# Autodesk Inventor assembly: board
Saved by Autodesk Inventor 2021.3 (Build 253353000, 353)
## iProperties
Created: 2021-12
Part Number: board
Document SubType Name: Assembly
Designer: Administrator
Title: board v1
Author: Administrator
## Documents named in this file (3)
- c:\worker\convert-fusion-r08\tmp\job-1\42\output\files\5687be83-607c-4978-9340-54991ac6dc59\board v1.iam
- c:\worker\convert-fusion-r08\tmp\job-1\42\output\files\5687be83-607c-4978-9340-54991ac6dc59\Board.ipt
- c:\worker\convert-fusion-r08\tmp\job-1\42\output\files\5687be83-607c-4978-9340-54991ac6dc59\Packages.iam
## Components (2 placed, 2 different names)
1. Board:1
2. Packages:1 [sub-assembly]
